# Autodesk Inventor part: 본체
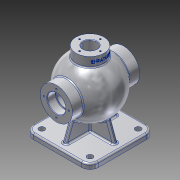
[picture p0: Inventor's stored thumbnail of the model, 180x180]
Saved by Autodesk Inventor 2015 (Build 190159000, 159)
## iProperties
Created: 2025-08
Part Number: 본체
Material: 알루미늄 6061
Document SubType Name: Modeling
Designer: user
Density: 2.7 g/cm^3
Appearance: 알루미늄 - 평지
Author: user
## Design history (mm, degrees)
sketch "스케치1"
  geometry: L1 (65, 0)-(65, 31); L2 (-65, 31)-(-65, 0); L3 (-65, -31)-(65, 31); L4 (65, -31)-(-65, 31); L5 (65, 31)-(44.215, 31); L6 (-44.215, 31)-(-65, 31); L7 (-65, 0)-(-44, 0); L8 (44, 0)-(65, 0); A1 r 54 centre (0, 0) between (44.215, 31) and (-44.215, 31); A2 r 44 centre (0, 0) between (44, 0) and (-44, 0); 1 further point
  constraints: 16 end point, 4 point on circle, 2 centre point, 2 coincident, 2 midpoint, 2 parallel, 1 horizontal, 1 vertical
  dimensions: "d0" = 108 diameter of A1; "d1" = 130 distance of L1.end L2.start; "d2" = 62 distance of L4.start L1.end; "d3" = 88 diameter of A2; "d4" = 90 deg angle of L1 L5; "d5" = 90 deg angle of L1 L8; "d6" = 64.5024 deg angle of L1 L4; "d7" = 64.5024 deg angle of L1 L3; "d8" = 130 distance between parallel lines of L1 L2; "d9" = 31 distance between parallel lines of L7 L6; "d10" = 0 distance from line of point (0, 0) L8; "d11" = 130 distance from line of L3.start L1
revolve "회전1" sketch "스케치1" stored, may be unused: angle "d12" = 90 deg
hole "구멍1" diameter "d15" = 30; stored, may be unused: countersink angle "d19" = 90 deg, drill point angle "d21" = 118 deg; dims "d13" = 10, "d14" = 10, "d16" = 6, "d17" = 35, "d18" = 16, "d20" = 8
node "작업 평면1"
sketch "스케치2"
  geometry: L1 (62.5, -62.5)-(-62.5, -62.5); L2 (-62.5, -62.5)-(-62.5, 62.5); L3 (-62.5, 62.5)-(62.5, 62.5); L4 (62.5, 62.5)-(62.5, -62.5); L5 (62.5, -62.5)-(-62.5, 62.5); L6 (-62.5, -62.5)-(62.5, 62.5); 1 further point
  constraints: 12 end point, 2 midpoint, 2 parallel, 1 horizontal, 1 perpendicular
  dimensions: "d23" = 125 distance of L2.end L3.end; "d24" = 125 distance of L1.end L2.end
extrude "돌출1" join sketch "스케치2" distance "d25" = 10; taper "d26" = 0 deg
sketch "스케치3"
  geometry: L1 (4, -50.5)-(-4, -50.5); L2 (-4, -50.5)-(-4, 50.5); L3 (-4, 50.5)-(4, 50.5); L4 (4, 50.5)-(4, -50.5); L5 (4, -50.5)-(-4, 50.5); L6 (-4, -50.5)-(4, 50.5); L7 (50.5, -4)-(-50.5, -4); L8 (-50.5, -4)-(-50.5, 4); L9 (-50.5, 4)-(50.5, 4); L10 (50.5, 4)-(50.5, -4); L11 (50.5, -4)-(-50.5, 4); L12 (-50.5, -4)-(50.5, 4); L13 (62.5, -62.5)-(-62.5, -62.5) reference; L14 (-62.5, -62.5)-(-62.5, 62.5) reference; 1 further point
  constraints: 24 end point, 4 midpoint, 4 parallel, 2 horizontal, 2 perpendicular
  dimensions: "d27" = 12 distance between parallel lines of L1 L13; "d28" = 12 distance between parallel lines of L14 L8; "d29" = 8 distance of L7.end L8.end; "d30" = 8 distance of L2.end L3.end
extrude "돌출2" join sketch "스케치3" stored distance "d31" = 10; taper "d32" = 0 deg
feature "면 기울기1" dims angle "d33" = 20 deg
feature "면 기울기2" dims angle "d34" = 20 deg
fillet "모깎기1" dims "d35" = 16
hole "구멍2" diameter "d38" = 11; stored, may be unused: countersink angle "d42" = 90 deg, drill point angle "d44" = 118 deg; dims "d36" = 10, "d37" = 10, "d39" = 6, "d40" = 35, "d41" = 16, "d43" = 8
hole "구멍3" diameter "d47" = 11; stored, may be unused: countersink angle "d51" = 90 deg, drill point angle "d53" = 118 deg; dims "d45" = 10, "d46" = 10, "d48" = 6, "d49" = 35, "d50" = 16, "d52" = 8
hole "구멍4" diameter "d56" = 11; stored, may be unused: countersink angle "d60" = 90 deg, drill point angle "d62" = 118 deg; dims "d54" = 10, "d55" = 10, "d57" = 6, "d58" = 35, "d59" = 16, "d61" = 8
hole "구멍5" diameter "d65" = 11; stored, may be unused: countersink angle "d69" = 90 deg, drill point angle "d71" = 118 deg; dims "d63" = 10, "d64" = 10, "d66" = 6, "d67" = 35, "d68" = 16, "d70" = 8
sketch "스케치4"
  geometry: L1 (0, 0)-(0, 24)
  constraints: 2 end point, 1 vertical
  dimensions: "d72" = 24 distance of L1.start L1.end
hole "구멍6" sketch "스케치4" at (0, 24) diameter "d73" = 3.242; stored, may be unused: countersink angle "d77" = 90 deg, drill point angle "d79" = 118 deg; dims "d74" = 12, "d75" = 35, "d76" = 16, "d78" = 15
node "작업 평면2"
sketch "스케치5"
  geometry: C1 r 27 at (0, 0); 1 further point
  constraints: 1 centre point, 1 coincident
  dimensions: "d84" = 54 diameter of C1
extrude "돌출3" join sketch "스케치5" stored distance "d85" = 10; taper "d86" = 0 deg
hole "구멍7" diameter "d89" = 26; stored, may be unused: countersink angle "d93" = 90 deg, drill point angle "d95" = 118 deg; dims "d87" = 10, "d88" = 10, "d90" = 12, "d91" = 35, "d92" = 16, "d94" = 50
sketch "스케치6"
  geometry: L1 (0, 0)-(0, 20)
  constraints: 2 end point, 1 vertical
  dimensions: "d96" = 20 distance of L1.start L1.end
hole "구멍8" sketch "스케치6" at (0, 20) diameter "d97" = 3.242; stored, may be unused: countersink angle "d101" = 90 deg, drill point angle "d103" = 118 deg; dims "d98" = 9, "d99" = 35, "d100" = 16, "d102" = 11
fillet "모깎기2" dims "d107" = 0.6
fillet "모깎기3" dims "d108" = 3
fillet "모깎기4" dims "d109" = 3
fillet "모깎기5" dims "d110" = 3
fillet "모깎기6" dims "d111" = 3
node "작업 평면3"
sketch "스케치7"
  geometry: L1 (-27, 65)-(27, 65) reference; 2 further points
  constraints: 1 vertical alignment, 1 other
  dimensions: "d113" = 9 distance from line of point (0, 56) L1
feature "엠보싱1" sketch "스케치7" dims "d20" = 8, "d114" = 0.5, "d115" = 0
chamfer "모따기1" distance "d116" = 1; stored, may be unused: second distance "d117" = 2, angle "d118" = 45 deg
node "솔리드1"
mirror "대칭1"
pattern_circular "원형 패턴1" dims angle "d81" = 360 deg
mirror "대칭2"
pattern_circular "원형 패턴2" dims angle "d105" = 360 deg
other parameters: "d22" = -85, "d112" = 133.5
